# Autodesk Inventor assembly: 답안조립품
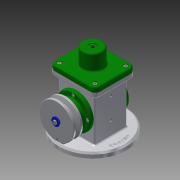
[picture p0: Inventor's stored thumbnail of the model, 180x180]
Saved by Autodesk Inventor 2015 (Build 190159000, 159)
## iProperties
Created: 2019-08
Part Number: 답안조립품
Document SubType Name: Assembly
Designer: now060
Author: now060
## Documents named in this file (18)
- C:\Users\now060\Desktop\490804V1028\답안조립품.iam
- C:\Users\now060\Desktop\490804V1028\E-링.ipt
- C:\Users\now060\Desktop\490804V1028\V-벨트풀리.ipt
- C:\Users\now060\Desktop\490804V1028\덮개.ipt
- C:\Users\now060\Desktop\490804V1028\뒤커버.ipt
- C:\Users\now060\Desktop\490804V1028\링크.ipt
- C:\Users\now060\Desktop\490804V1028\베어링 17 x 40 x 12.ipt
- C:\Users\now060\Desktop\490804V1028\본체.ipt
- C:\Users\now060\Desktop\490804V1028\볼트 M4 x 8.ipt
- C:\Users\now060\Desktop\490804V1028\볼트 M4 x 10.ipt
- C:\Users\now060\Desktop\490804V1028\슬라이더.ipt
- C:\Users\now060\Desktop\490804V1028\앞커버.ipt
- C:\Users\now060\Desktop\490804V1028\오일 실 17 30 8.ipt
- C:\Users\now060\Desktop\490804V1028\와셔 4x16.ipt
- C:\Users\now060\Desktop\490804V1028\클레비스 핀 6 x 22.ipt
- 클레비스 핀 6 x 22.ipt
- C:\Users\now060\Desktop\490804V1028\키 4 x 4 x 12.ipt
- C:\Users\now060\Desktop\490804V1028\편심축.ipt
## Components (2 placed, 2 different names)
1. E-링:1
2. V-벨트풀리:1 — 각도:2
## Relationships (1: Angle 1)
- 각도:2 [Angle]: V-벨트풀리:1
